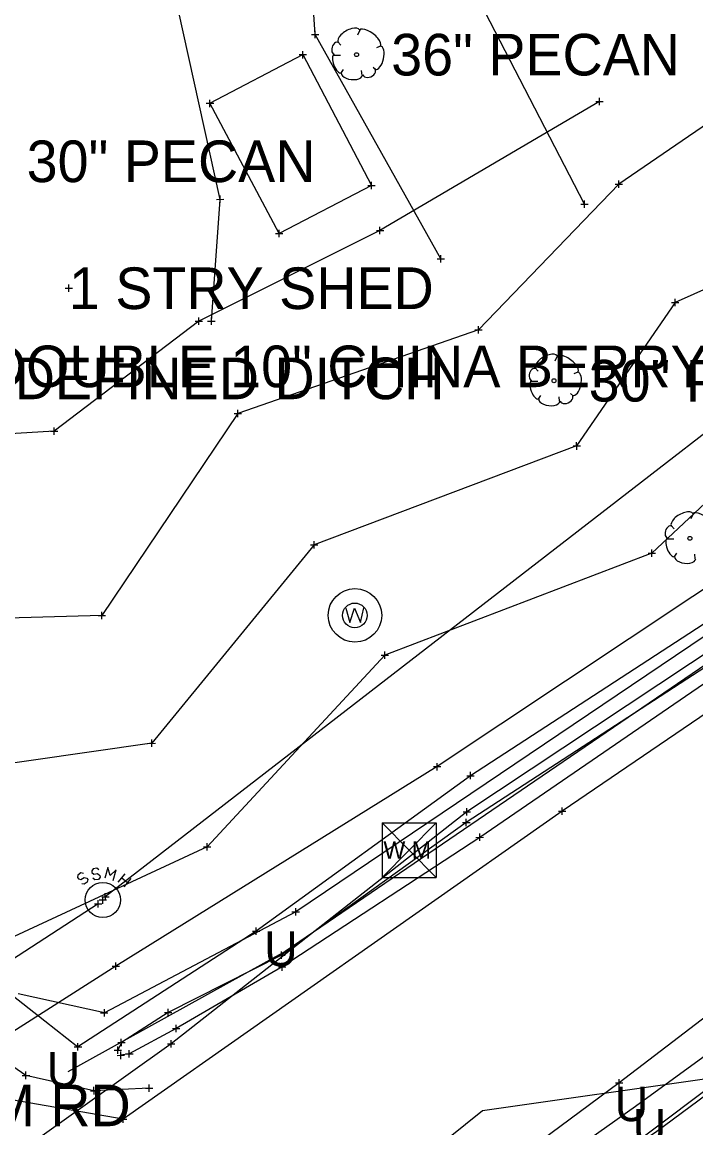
# Model space of a CAD drawing. Extents: x -1 to 1157254, y -1 to 2021979.
# Drawn here: x 1150407.3 to 1150523.9, y 2019736.2 to 2019927.5 of the extents above; entities that cross this region are included whole.
import ezdxf

# ---------------------------------------------------------------- set-up
doc = ezdxf.new("R2010")
doc.units = 0
for name, color, linetype in [('S_BUILDING_ANNOT', 7, 'Continuous'), ('S_CAL_CORNER_ANNOT', 7, 'Continuous'), ('S_CONTOUR_ANNOT', 7, 'Continuous'), ('S_CONTOUR_MAJOR', 7, 'Continuous'), ('S_CONTOUR_MINOR', 7, 'Continuous'), ('S_CTL_TABLE', 7, 'Continuous'), ('S_CURB', 7, 'Continuous'), ('S_CURB_ANNOT', 7, 'Continuous'), ('S_DRIVEWAY_ANNOT', 7, 'Continuous'), ('S_DROP_INLET', 7, 'Continuous'), ('S_EDGE_BITUMINOUS_ANNOT', 7, 'Continuous'), ('S_EDGE_CONCRETE', 7, 'Continuous'), ('S_FENCE', 7, 'Continuous'), ('S_FLAG_POLE_ANNOT', 7, 'Continuous'), ('S_GAS_PUMP_ISLAND_ANNOT', 7, 'Continuous'), ('S_GATE', 7, 'Continuous'), ('S_GATE_ANNOT', 7, 'Continuous')]:
    doc.layers.add(name, color=color, linetype=linetype)

msp = doc.modelspace()

# ---------------------------------------------------------------- linework, layer by layer
at = {"layer": 'S_BUILDING_ANNOT'}
for p, q in [((1150455.87, 2019921.22), (1150455.87, 2019922.49)), ((1150455.23, 2019921.86), (1150456.51, 2019921.86)), ((1150455.87, 2019921.86), (1150455.87, 2019921.86)), ((1150439.14, 2019913.44), (1150440.42, 2019913.44)), ((1150439.78, 2019912.8), (1150439.78, 2019914.07)), ((1150439.78, 2019913.44), (1150439.78, 2019913.44)), ((1150467.07, 2019899.22), (1150468.34, 2019899.22)), ((1150467.71, 2019898.59), (1150467.71, 2019899.86)), ((1150467.71, 2019899.22), (1150467.71, 2019899.22)), ((1150451.12, 2019890.93), (1150452.39, 2019890.93)), ((1150451.75, 2019890.29), (1150451.75, 2019891.56)), ((1150451.75, 2019890.93), (1150451.75, 2019890.93)), ((1150415.37, 2019880.81), (1150415.37, 2019882.09)), ((1150414.73, 2019881.45), (1150416, 2019881.45)), ((1150415.37, 2019881.45), (1150415.37, 2019881.45)), ((1150478.48, 2019798.68), (1150479.75, 2019798.68)), ((1150479.12, 2019798.04), (1150479.11, 2019799.31)), ((1150479.12, 2019798.68), (1150479.12, 2019798.68)), ((1150483.61, 2019790.85), (1150484.88, 2019790.85)), ((1150484.25, 2019790.21), (1150484.25, 2019791.49)), ((1150484.25, 2019790.85), (1150484.25, 2019790.85)), ((1150500.11, 2019790.99), (1150501.38, 2019790.99)), ((1150500.75, 2019790.35), (1150500.75, 2019791.63)), ((1150500.75, 2019790.99), (1150500.75, 2019790.99)), ((1150483.5, 2019789.03), (1150484.78, 2019789.03)), ((1150484.14, 2019788.4), (1150484.14, 2019789.67)), ((1150484.14, 2019789.03), (1150484.14, 2019789.03)), ((1150485.81, 2019786.45), (1150487.09, 2019786.46)), ((1150486.45, 2019785.82), (1150486.45, 2019787.09)), ((1150486.45, 2019786.45), (1150486.45, 2019786.45)), ((1150421.68, 2019775.54), (1150421.67, 2019776.81)), ((1150421.68, 2019775.54), (1150421.67, 2019776.81)), ((1150419.82, 2019774.94), (1150421.09, 2019774.94)), ((1150419.82, 2019774.94), (1150421.09, 2019774.94)), ((1150420.46, 2019774.31), (1150420.46, 2019775.58)), ((1150420.46, 2019774.31), (1150420.46, 2019775.58)), ((1150420.46, 2019774.94), (1150420.46, 2019774.94)), ((1150420.46, 2019774.94), (1150420.46, 2019774.94)), ((1150420.6, 2019775.61), (1150421.88, 2019775.61)), ((1150421.04, 2019776.18), (1150422.31, 2019776.18)), ((1150421.04, 2019776.18), (1150422.31, 2019776.18)), ((1150421.24, 2019774.97), (1150421.24, 2019776.24)), ((1150421.24, 2019775.61), (1150421.24, 2019775.61)), ((1150421.67, 2019776.18), (1150421.67, 2019776.18)), ((1150421.67, 2019776.18), (1150421.67, 2019776.18)), ((1150453.97, 2019773.54), (1150455.25, 2019773.54)), ((1150454.61, 2019772.9), (1150454.61, 2019774.18)), ((1150454.61, 2019773.54), (1150454.61, 2019773.54)), ((1150451.51, 2019766.06), (1150452.78, 2019766.07)), ((1150452.15, 2019765.43), (1150452.14, 2019766.7)), ((1150452.15, 2019766.06), (1150452.15, 2019766.06)), ((1150422.83, 2019764.16), (1150424.11, 2019764.16)), ((1150423.47, 2019763.52), (1150423.47, 2019764.79)), ((1150423.47, 2019764.16), (1150423.47, 2019764.16)), ((1150451.65, 2019764.02), (1150452.92, 2019764.02)), ((1150452.29, 2019763.38), (1150452.28, 2019764.66)), ((1150452.29, 2019764.02), (1150452.29, 2019764.02)), ((1150420.86, 2019756.1), (1150422.13, 2019756.1)), ((1150421.5, 2019755.46), (1150421.5, 2019756.73)), ((1150421.5, 2019756.1), (1150421.5, 2019756.1)), ((1150431.93, 2019756.16), (1150433.2, 2019756.16)), ((1150432.57, 2019755.53), (1150432.57, 2019756.8)), ((1150432.57, 2019756.16), (1150432.57, 2019756.16)), ((1150433.91, 2019752.72), (1150433.91, 2019753.99)), ((1150433.28, 2019753.35), (1150434.55, 2019753.35)), ((1150433.91, 2019753.35), (1150433.91, 2019753.35)), ((1150423.81, 2019750.95), (1150425.08, 2019750.95)), ((1150423.85, 2019748.98), (1150423.85, 2019750.26)), ((1150424.45, 2019750.32), (1150424.44, 2019751.59)), ((1150424.45, 2019750.95), (1150424.45, 2019750.95)), ((1150432.44, 2019750.74), (1150433.72, 2019750.74)), ((1150433.08, 2019750.1), (1150433.08, 2019751.38)), ((1150433.08, 2019750.74), (1150433.08, 2019750.74)), ((1150423.21, 2019749.62), (1150424.48, 2019749.62)), ((1150423.72, 2019748.73), (1150425, 2019748.74)), ((1150423.85, 2019749.62), (1150423.85, 2019749.62)), ((1150424.36, 2019748.1), (1150424.36, 2019749.37)), ((1150424.36, 2019748.74), (1150424.36, 2019748.74)), ((1150425.19, 2019748.97), (1150426.46, 2019748.97)), ((1150425.82, 2019748.34), (1150425.82, 2019749.61)), ((1150425.82, 2019748.97), (1150425.82, 2019748.97)), ((1150407.31, 2019745.27), (1150408.58, 2019745.27)), ((1150407.94, 2019744.64), (1150407.94, 2019745.91)), ((1150407.94, 2019745.27), (1150407.94, 2019745.27)), ((1150510.58, 2019743.33), (1150510.57, 2019744.61)), ((1150419.08, 2019742.62), (1150420.35, 2019742.62)), ((1150419.72, 2019741.98), (1150419.71, 2019743.26)), ((1150419.71, 2019742.62), (1150419.71, 2019742.62)), ((1150428.61, 2019743.04), (1150429.88, 2019743.05)), ((1150429.24, 2019742.41), (1150429.24, 2019743.68)), ((1150429.24, 2019743.04), (1150429.24, 2019743.04)), ((1150509.94, 2019743.97), (1150511.21, 2019743.97)), ((1150510.58, 2019743.97), (1150510.58, 2019743.97)), ((1150424.14, 2019737.67), (1150425.41, 2019737.67)), ((1150424.78, 2019737.03), (1150424.77, 2019738.31)), ((1150424.78, 2019737.67), (1150424.78, 2019737.67))]:
    msp.add_line(p, q, dxfattribs=at)
at = {"layer": 'S_CAL_CORNER_ANNOT'}
for points in [[(1150827.62, 2020008.19), (1150733.09, 2019947.48), (1150628.16, 2019877.65), (1150500.75, 2019790.99), (1150424.78, 2019737.67), (1150355.4, 2019749.66)], [(1150682.05, 2019865.85), (1150601.54, 2019813.47), (1150510.58, 2019743.97), (1150405.28, 2019665.92), (1150310.69, 2019593.56), (1150188.92, 2019499.64), (1150039.45, 2019388.15), (1149962.15, 2019331.17), (1149944.63, 2019319.08), (1149774.15, 2019191.52), (1149712.73, 2019145.6), (1149665.81, 2019108.74), (1149605.46, 2019057.66), (1149527.46, 2018983.58), (1149450.12, 2018902.93), (1149278.32, 2018738.82), (1149257.2, 2018716.38), (1149237.23, 2018691.25), (1149165.09, 2018617.77), (1149125.26, 2018579.57), (1149069.5, 2018523.84), (1149012.03, 2018473.77), (1148938.88, 2018408.55)]]:
    msp.add_lwpolyline(points, dxfattribs=at)
at = {"layer": 'S_CONTOUR_ANNOT'}
for p, q in [((1150469.59, 2019788.98), (1150478.92, 2019788.98)), ((1150469.59, 2019788.98), (1150469.59, 2019779.49)), ((1150469.59, 2019788.98), (1150478.92, 2019779.49)), ((1150478.92, 2019788.98), (1150469.59, 2019779.49)), ((1150478.92, 2019788.98), (1150478.92, 2019779.49)), ((1150469.59, 2019779.49), (1150478.92, 2019779.49))]:
    msp.add_line(p, q, dxfattribs=at)
for points in [[(1150857.08, 2020031.73), (1150832.22, 2020016.43), (1150747.37, 2019963.08), (1150692.94, 2019929.63), (1150639.49, 2019893), (1150583.9, 2019856.96), (1150484.25, 2019790.85), (1150433.08, 2019750.74), (1150355.8, 2019695.65), (1150341.28, 2019681.73), (1150287.94, 2019641.18), (1150216.41, 2019587.25), (1150034.4, 2019445.88), (1149979.98, 2019405.6), (1149934.92, 2019374.11), (1149784.56, 2019258.12)], [(1150776.08, 2020000.06), (1150711.77, 2019956.26), (1150627.27, 2019900.66), (1150578.77, 2019864.96), (1150479.12, 2019798.68), (1150423.47, 2019764.16), (1150358.5, 2019722.73), (1150313.96, 2019690.01), (1150273.95, 2019661.03), (1150225.64, 2019623.26), (1150033.5, 2019468.9), (1149971.69, 2019423.78), (1149931.59, 2019393.98), (1149688.42, 2019230.92)]]:
    msp.add_lwpolyline(points, dxfattribs=at)
at = {"layer": 'S_CONTOUR_MINOR'}
for p, q in [((1150416.92, 2019779.91), (1150416.84, 2019779.52)), ((1150416.84, 2019779.52), (1150417.03, 2019779.25)), ((1150417.46, 2019780.3), (1150416.92, 2019779.91)), ((1150417.03, 2019779.25), (1150417.46, 2019779.13)), ((1150417.88, 2019780.22), (1150417.46, 2019780.3)), ((1150417.46, 2019779.13), (1150418, 2019779.48)), ((1150418, 2019779.48), (1150418.46, 2019779.41)), ((1150418.54, 2019778.71), (1150418, 2019778.32)), ((1150418.46, 2019779.41), (1150418.62, 2019779.13)), ((1150418.62, 2019779.13), (1150418.54, 2019778.71)), ((1150423.89, 2019778.67), (1150425.13, 2019780.14)), ((1150424.55, 2019779.44), (1150425.51, 2019778.63)), ((1150426.1, 2019779.33), (1150424.86, 2019777.86)), ((1150418, 2019778.32), (1150417.61, 2019778.4))]:
    msp.add_line(p, q, dxfattribs=at)
for points in [[(1150622.8, 2019931.71), (1150421.67, 2019776.18)], [(1150420.56, 2019780.84), (1150420.21, 2019781.11), (1150419.55, 2019781.03), (1150419.32, 2019780.68), (1150419.36, 2019780.37), (1150419.7, 2019780.06), (1150420.32, 2019780.18), (1150420.71, 2019779.87), (1150420.75, 2019779.56), (1150420.48, 2019779.17), (1150419.86, 2019779.1), (1150419.51, 2019779.37)], [(1150423, 2019778.98), (1150423.54, 2019780.84), (1150422.49, 2019779.83), (1150422.11, 2019781.26), (1150421.56, 2019779.41)], [(1150420.46, 2019774.94), (1150330.39, 2019716.45)]]:
    msp.add_lwpolyline(points, dxfattribs=at)
msp.add_circle((1150421.24, 2019775.61), 3.05, dxfattribs=at)
at = {"layer": 'S_CTL_TABLE'}
for p, q in [((1150457.34, 2019925.36), (1150458.61, 2019925.36)), ((1150457.98, 2019924.72), (1150457.97, 2019926)), ((1150457.98, 2019925.36), (1150457.98, 2019925.36)), ((1150506.55, 2019913.76), (1150507.83, 2019913.77)), ((1150507.19, 2019913.13), (1150507.19, 2019914.4)), ((1150507.19, 2019913.76), (1150507.19, 2019913.76)), ((1150509.89, 2019899.44), (1150511.16, 2019899.45)), ((1150510.52, 2019898.81), (1150510.52, 2019900.08)), ((1150510.52, 2019899.45), (1150510.52, 2019899.45)), ((1150441.56, 2019896.2), (1150441.56, 2019897.47)), ((1150440.92, 2019896.83), (1150442.2, 2019896.84)), ((1150441.56, 2019896.83), (1150441.56, 2019896.83)), ((1150503.97, 2019896), (1150505.24, 2019896.01)), ((1150504.6, 2019895.37), (1150504.6, 2019896.64)), ((1150504.6, 2019896), (1150504.6, 2019896)), ((1150469.2, 2019890.82), (1150469.2, 2019892.09)), ((1150468.57, 2019891.45), (1150469.84, 2019891.46)), ((1150469.2, 2019891.46), (1150469.2, 2019891.46)), ((1150479.07, 2019886.54), (1150480.34, 2019886.54)), ((1150479.71, 2019885.9), (1150479.71, 2019887.17)), ((1150479.71, 2019886.54), (1150479.71, 2019886.54)), ((1150519.64, 2019878.98), (1150520.91, 2019878.98)), ((1150520.27, 2019878.34), (1150520.27, 2019879.62)), ((1150520.27, 2019878.98), (1150520.27, 2019878.98)), ((1150437.88, 2019875.12), (1150437.87, 2019876.39)), ((1150440.02, 2019875.12), (1150440.02, 2019876.39)), ((1150437.24, 2019875.75), (1150438.51, 2019875.76)), ((1150437.87, 2019875.75), (1150437.87, 2019875.75)), ((1150439.38, 2019875.75), (1150440.65, 2019875.75)), ((1150440.02, 2019875.75), (1150440.02, 2019875.75)), ((1150486.25, 2019873.63), (1150486.25, 2019874.9)), ((1150485.61, 2019874.26), (1150486.88, 2019874.27)), ((1150486.25, 2019874.27), (1150486.25, 2019874.27)), ((1150443.95, 2019859.77), (1150445.22, 2019859.77)), ((1150444.58, 2019859.13), (1150444.58, 2019860.41)), ((1150444.58, 2019859.77), (1150444.58, 2019859.77)), ((1150412.82, 2019856.07), (1150412.82, 2019857.34)), ((1150412.19, 2019856.71), (1150413.46, 2019856.71)), ((1150412.82, 2019856.71), (1150412.82, 2019856.71)), ((1150502.6, 2019854.16), (1150503.87, 2019854.16)), ((1150503.24, 2019853.52), (1150503.23, 2019854.79)), ((1150503.23, 2019854.16), (1150503.23, 2019854.16)), ((1150457.17, 2019837.03), (1150458.44, 2019837.04)), ((1150457.8, 2019836.4), (1150457.8, 2019837.67)), ((1150457.8, 2019837.04), (1150457.8, 2019837.04)), ((1150516.22, 2019834.99), (1150516.22, 2019836.27)), ((1150515.58, 2019835.63), (1150516.86, 2019835.63)), ((1150516.22, 2019835.63), (1150516.22, 2019835.63)), ((1150420.43, 2019824.82), (1150421.7, 2019824.82)), ((1150421.06, 2019824.19), (1150421.06, 2019825.46)), ((1150421.06, 2019824.82), (1150421.06, 2019824.82)), ((1150469.39, 2019817.99), (1150470.66, 2019817.99)), ((1150470.03, 2019817.36), (1150470.02, 2019818.63)), ((1150470.03, 2019817.99), (1150470.03, 2019817.99)), ((1150429.05, 2019802.71), (1150430.33, 2019802.72)), ((1150429.69, 2019802.08), (1150429.69, 2019803.35)), ((1150429.69, 2019802.72), (1150429.69, 2019802.72)), ((1150484.21, 2019797.12), (1150485.48, 2019797.12)), ((1150484.84, 2019796.49), (1150484.84, 2019797.76)), ((1150484.84, 2019797.12), (1150484.84, 2019797.12)), ((1150438.68, 2019784.83), (1150439.95, 2019784.83)), ((1150439.32, 2019784.19), (1150439.31, 2019785.47)), ((1150439.32, 2019784.83), (1150439.32, 2019784.83)), ((1150447.12, 2019770.22), (1150448.39, 2019770.22)), ((1150447.76, 2019769.58), (1150447.76, 2019770.85)), ((1150447.76, 2019770.22), (1150447.76, 2019770.22)), ((1150416.29, 2019750.2), (1150417.56, 2019750.2)), ((1150416.3, 2019750.23), (1150417.58, 2019750.23)), ((1150416.92, 2019749.57), (1150416.92, 2019750.84)), ((1150416.92, 2019750.2), (1150416.92, 2019750.2)), ((1150416.94, 2019749.59), (1150416.94, 2019750.86)), ((1150416.94, 2019750.23), (1150416.94, 2019750.23))]:
    msp.add_line(p, q, dxfattribs=at)
at = {"layer": 'S_CURB'}
for p, q in [((1150465.7, 2019926.11), (1150465.31, 2019925.26)), ((1150461.91, 2019924.09), (1150462.41, 2019923.51)), ((1150469.27, 2019923.32), (1150468.61, 2019923.05)), ((1150461.25, 2019921.77), (1150462.37, 2019921.77)), ((1150462.41, 2019918.59), (1150462.87, 2019919.29)), ((1150466.09, 2019918.32), (1150466.01, 2019919.1)), ((1150468.49, 2019919.21), (1150468.03, 2019919.64)), ((1150499.87, 2019869.7), (1150499.48, 2019868.84)), ((1150496.07, 2019867.68), (1150496.57, 2019867.1)), ((1150503.43, 2019866.91), (1150502.77, 2019866.64)), ((1150495.41, 2019865.36), (1150496.54, 2019865.36)), ((1150496.57, 2019862.18), (1150497.04, 2019862.88)), ((1150502.66, 2019862.8), (1150502.19, 2019863.23)), ((1150500.25, 2019861.91), (1150500.18, 2019862.68)), ((1150523.38, 2019842.43), (1150522.99, 2019841.58)), ((1150519.58, 2019840.41), (1150520.08, 2019839.83)), ((1150518.92, 2019838.09), (1150520.05, 2019838.09)), ((1150520.08, 2019834.91), (1150520.55, 2019835.61)), ((1150523.76, 2019834.64), (1150523.69, 2019835.42))]:
    msp.add_line(p, q, dxfattribs=at)
for centre in [(1150465.14, 2019921.86), (1150499.31, 2019865.45), (1150522.82, 2019838.18)]:
    msp.add_circle(centre, 0.34, dxfattribs=at)
for centre, major_axis, ratio, start_param, end_param in [((1150463.81, 2019925.07), (1.86, 1.08), 0.471018, 0, 3.141593), ((1150467.46, 2019924.74), (-1.81, 1.36), 0.405113, 3.141593, 6.283186), ((1150461.57, 2019922.95), (0.31, 1.03), 0.646762, 0, 3.141593), ((1150468.82, 2019921.34), (0.46, 2.04), 0.482994, 3.141593, 6.283185), ((1150461.88, 2019920.3), (-0.61, 1.6), 0.420543, 6.283185, 9.424777), ((1150464.34, 2019918.52), (-1.83, 0.19), 0.529943, 0, 3.141593), ((1150467.3, 2019918.82), (1.09, 0.46), 0.711534, 3.141592, 6.283185), ((1150497.97, 2019868.65), (1.86, 1.08), 0.471018, 0, 3.141593), ((1150501.63, 2019868.33), (-1.81, 1.36), 0.405113, 3.141593, 6.283186), ((1150495.74, 2019866.54), (0.31, 1.03), 0.646762, 0, 3.141593), ((1150502.98, 2019864.92), (0.46, 2.04), 0.482994, 3.141593, 6.283185), ((1150496.04, 2019863.89), (-0.61, 1.6), 0.420543, 6.283185, 9.424777), ((1150498.5, 2019862.11), (-1.83, 0.19), 0.529943, 0, 3.141593), ((1150501.46, 2019862.4), (1.09, 0.46), 0.711534, 3.141592, 6.283185), ((1150521.48, 2019841.38), (1.86, 1.08), 0.471018, 0, 3.141593), ((1150525.14, 2019841.06), (-1.81, 1.36), 0.405113, 3.141593, 6.283186), ((1150519.25, 2019839.27), (0.31, 1.03), 0.646762, 0, 3.141593), ((1150519.56, 2019836.62), (-0.61, 1.6), 0.420543, 6.283185, 9.424777), ((1150522.01, 2019834.84), (-1.83, 0.19), 0.529943, 0, 3.141593)]:
    msp.add_ellipse(centre, major_axis=major_axis, ratio=ratio, start_param=start_param, end_param=end_param, dxfattribs=at)
at = {"layer": 'S_CURB_ANNOT'}
for p, q in [((1150463.31, 2019826.11), (1150463.97, 2019823.63)), ((1150463.97, 2019823.63), (1150464.78, 2019826.11)), ((1150464.78, 2019826.11), (1150465.83, 2019823.63)), ((1150465.83, 2019823.63), (1150466.41, 2019826.15))]:
    msp.add_line(p, q, dxfattribs=at)
for centre, radius in [((1150464.87, 2019824.85), 4.63), ((1150464.84, 2019824.85), 2.13)]:
    msp.add_circle(centre, radius, dxfattribs=at)
at = {"layer": 'S_DRIVEWAY_ANNOT'}
for points in [[(1150598.96, 2019864.81), (1150597.2, 2019863.93), (1150584.79, 2019854.84), (1150547.42, 2019831.48), (1150531.17, 2019819.56), (1150484.14, 2019789.03), (1150452.15, 2019766.06), (1150432.57, 2019756.16), (1150424.45, 2019750.95), (1150423.85, 2019749.62)], [(1150599.27, 2019863.57), (1150597.85, 2019862.02), (1150585.83, 2019852.79), (1150548.91, 2019829.11), (1150532.32, 2019817.84), (1150486.45, 2019786.45), (1150452.29, 2019764.02), (1150433.91, 2019753.35), (1150425.82, 2019748.97), (1150424.36, 2019748.74)]]:
    msp.add_lwpolyline(points, dxfattribs=at)
at = {"layer": 'S_DROP_INLET'}
for points in [[(1150831.49, 2020022.11), (1150729.58, 2019954.73), (1150690.81, 2019927.93), (1150657.92, 2019906.59), (1150452.8, 2019766.7), (1150415.16, 2019745.86)], [(1150852.18, 2019973.05), (1150778.54, 2019928.45), (1150770.16, 2019919.18), (1150703.8, 2019877.29), (1150608.63, 2019809.12), (1150513.43, 2019739.89), (1150405.92, 2019663.65), (1150352.2, 2019622.72), (1150343.81, 2019614.74), (1150336.72, 2019606.98), (1150314.89, 2019591.84), (1150193.25, 2019498.28), (1150112.69, 2019435.49), (1150059.59, 2019406.16), (1150037.88, 2019389.79), (1149962.99, 2019329.91), (1149914.05, 2019297.4), (1149863.26, 2019256.98)], [(1150853.56, 2019969.99), (1150781.71, 2019924.44), (1150774.41, 2019914.43), (1150697.13, 2019863.12), (1150609.24, 2019805.57), (1150516.58, 2019735.98), (1150408.74, 2019655.56), (1150359.48, 2019622.09), (1150352.77, 2019615.32), (1150355.2, 2019603.6), (1150359.35, 2019593.87)]]:
    msp.add_lwpolyline(points, dxfattribs=at)
at = {"layer": 'S_EDGE_BITUMINOUS_ANNOT'}
for points in [[(1150440.02, 2019875.75), (1150441.56, 2019896.83), (1150433.42, 2019933.69), (1150420.68, 2019976.07), (1150426.42, 2020006.9), (1150427.82, 2020037.57), (1150429.36, 2020069.98), (1150438.58, 2020111.6), (1150432.5, 2020137.84), (1150435.46, 2020164.49), (1150434.53, 2020190.52)], [(1150504.6, 2019896), (1150481.4, 2019940.84), (1150483.75, 2019983.57), (1150467.93, 2020009.15), (1150462.66, 2020037.04), (1150480.19, 2020070.94), (1150487.22, 2020107.83), (1150474.53, 2020130.87), (1150477.72, 2020156.85), (1150472.41, 2020190.14)], [(1150479.71, 2019886.54), (1150457.98, 2019925.36), (1150454.71, 2019974.26), (1150450.93, 2020006.96), (1150446.48, 2020038.36), (1150456.89, 2020068.95), (1150464.77, 2020107.74), (1150451.6, 2020134.88), (1150458.51, 2020159.44), (1150452.29, 2020189.66)], [(1150535.91, 2019916.81), (1150510.52, 2019899.45), (1150486.25, 2019874.27), (1150444.58, 2019859.77), (1150421.06, 2019824.82), (1150386.3, 2019823.84)], [(1150507.19, 2019913.76), (1150469.2, 2019891.46), (1150437.87, 2019875.75), (1150412.82, 2019856.71), (1150388.11, 2019855.25), (1150386.3, 2019823.85)], [(1150566.44, 2019909.47), (1150551.45, 2019892.86), (1150520.27, 2019878.98), (1150503.23, 2019854.16), (1150457.8, 2019837.04), (1150429.69, 2019802.72), (1150387.5, 2019796.68)], [(1150582.96, 2019887.8), (1150572.99, 2019871.93), (1150534.64, 2019852.87), (1150516.22, 2019835.63), (1150470.03, 2019817.99), (1150439.32, 2019784.83), (1150396.89, 2019765.16)], [(1150596.26, 2019870.08), (1150583.12, 2019859.61), (1150544.16, 2019836.58), (1150526.3, 2019824.02), (1150484.84, 2019797.12), (1150447.76, 2019770.22), (1150416.92, 2019750.2)], [(1150387.53, 2019796.76), (1150393.99, 2019768.19), (1150416.94, 2019750.23)]]:
    msp.add_lwpolyline(points, dxfattribs=at)
at = {"layer": 'S_EDGE_CONCRETE'}
msp.add_lwpolyline([(1150429.24, 2019743.04), (1150419.71, 2019742.62), (1150407.94, 2019745.27), (1150394.14, 2019754.76), (1150389.34, 2019771.1), (1150384.28, 2019810.36), (1150385.39, 2019860.63), (1150387.47, 2019928.5), (1150391.21, 2019985.97), (1150394.29, 2020042.93)], dxfattribs=at)
at = {"layer": 'S_FENCE'}
for points in [[(1150830.5, 2020023.61), (1150689.74, 2019932.52), (1150654.37, 2019908.24), (1150454.61, 2019773.54), (1150421.5, 2019756.1), (1150406.6, 2019759.37)], [(1150775.16, 2019913.88), (1150697.15, 2019862.05), (1150611.54, 2019805.47), (1150516.86, 2019735.37), (1150402.98, 2019659.79), (1150352.98, 2019622.15), (1150350.25, 2019606.72), (1150331.34, 2019598.55), (1150196.24, 2019490.87), (1150043.62, 2019380.11), (1149966.77, 2019324.72), (1149934.21, 2019308.48), (1149916.33, 2019289.12), (1149866.68, 2019250.91)]]:
    msp.add_lwpolyline(points, dxfattribs=at)
at = {"layer": 'S_FLAG_POLE_ANNOT'}
msp.add_lwpolyline([(1150467.71, 2019899.22), (1150451.75, 2019890.93), (1150439.78, 2019913.44), (1150455.87, 2019921.86)], close=True, dxfattribs=at)
at = {"layer": 'S_GAS_PUMP_ISLAND_ANNOT'}
msp.add_lwpolyline([(1150475.18, 2019729.75), (1150486.94, 2019739.18), (1150527.36, 2019744.97), (1150530.87, 2019745.39), (1150533.26, 2019748.12), (1150533.67, 2019750.16), (1150547.31, 2019784.88), (1150559.34, 2019793.54), (1150571.53, 2019802.29), (1150616.62, 2019786.84), (1150617.46, 2019781.87), (1150618.41, 2019777.23), (1150619.34, 2019771.87), (1150620.18, 2019766.9), (1150620.46, 2019766.99), (1150620.64, 2019767.04), (1150619.8, 2019772.01), (1150645.46, 2019813.87), (1150647.12, 2019814.66), (1150656.68, 2019820.74), (1150672.01, 2019831.09), (1150695.8, 2019846.94)], dxfattribs=at)

# ---------------------------------------------------------------- texts
at = {"layer": 'S_CONTOUR_ANNOT'}
msp.add_text('W M', height=2.999, dxfattribs=at).set_placement((1150469.79, 2019782.75))
at = {"layer": 'S_CONTOUR_MAJOR'}
for p in [(1150449.17, 2019764.16), (1150411.53, 2019743.31), (1150509.81, 2019737.34), (1150512.95, 2019733.44)]:
    msp.add_text('U', height=6, dxfattribs=at).set_placement(p)
at = {"layer": 'S_GATE'}
for s, p in [('1 STRY SHED', (1150415.37, 2019877.85)), ('NO DEFINED DITCH', (1150388.88, 2019862.25)), ('SALEM RD', (1150376.84, 2019736.47))]:
    msp.add_text(s, height=7.2, dxfattribs=at).set_placement(p)
at = {"layer": 'S_GATE_ANNOT'}
for s, p in [('36" PECAN', (1150471.14, 2019918.26)), ('30" PECAN', (1150408.06, 2019899.81)), ('DOUBLE 10" CHINA BERRY', (1150401.01, 2019864.33)), ('30" PECAN', (1150505.31, 2019861.85))]:
    msp.add_text(s, height=7.2, dxfattribs=at).set_placement(p)

doc.saveas('drawing.dxf')
